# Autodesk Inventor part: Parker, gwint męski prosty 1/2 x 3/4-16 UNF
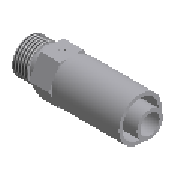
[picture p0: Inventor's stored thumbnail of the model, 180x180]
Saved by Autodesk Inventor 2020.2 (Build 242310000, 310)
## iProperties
IsCustomPart: 0
Company: Fabian Stasiak CAD Consulting
Manager: www.cadconsulting.pl
Created: 2014-02
Part Number: Parker, gwint męski prosty 1/2 x 3/4-16 UNF
Material: Stal
Description: Parker, łącznik
Document SubType Name: Modeling
Standard: Parker
Designer: F.Stasiak
Manufacturer: Parker
Language: pl-PL
Size Designation: 1/2 x 3/4-16 UNF
Categories: <MemberInstance><Categories><Category DisplayName="Rury cienko- i grubościenne" InternalName="4347fa0f-2144-441d-94cd-e3e15c92b736" Mnemonic="TUBEANDPIPE"><Cate
Density: 7.86 g/cm^3
Appearance: Płyta
Catalog Web Link: www.expertbooks.pl
NAME: PIPING: Parker Male Straight Thread
DATA: <meta><inlinegroups number="1" deflen="7.0358"></inlinegroups><connections number="2"></connections><angles><a>3.14159265358979</a></angles></meta>
Author: F.Stasiak
Subject: Zbiór ćwiczeń. Autodesk Inventor 2020. Kurs Professional
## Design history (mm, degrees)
sketch "Sketch1"
  geometry: L1 (0, 13.59)-(0, 3.51) reference; L2 (-14.176, 0)-(85.056, 0) reference; L3 (0, 4.95)-(0, 9.525); L4 (0, 9.525)-(8.6, 9.525); L5 (8.6, 9.525)-(8.6, 8.579); L6 (8.6, 8.579)-(10.725, 8.579); L7 (10.725, 8.579)-(10.725, 11.113); L8 (10.725, 11.113)-(23.984, 11.113); L9 (23.984, 11.113)-(23.984, 11.5); L10 (23.984, 11.5)-(27.784, 11.5); L11 (27.784, 11.5)-(27.784, 12.15); L12 (27.784, 12.15)-(62.484, 12.15); L13 (62.484, 12.15)-(62.484, 11.25); L14 (62.484, 11.25)-(35.18, 11.25); L15 (35.18, 11.25)-(35.18, 10.05); L16 (35.18, 10.05)-(30.48, 10.05); L17 (30.48, 10.05)-(30.48, 6.65); L18 (30.48, 6.65)-(70.88, 6.65); L19 (70.88, 6.65)-(70.88, 4.95); L20 (70.88, 4.95)-(0, 4.95)
  constraints: 36 end point, 14 parallel, 3 perpendicular, 1 point on line
  dimensions: "d0" = 9.9 diameter of L20 L2 (= HOLE); "d1" = 13.3 diameter of L18 L2 (= P1); "d2" = 20.1 diameter of L16 L2 (= U1); "d3" = 22.5 diameter of L14 L2 (= V1); "d4" = 24.3 diameter of L12 L2 (= SHELL_CRIMP); "d5" = 62.484 distance between parallel lines of L13 L1 (= A1); "d6" = 13.2588 distance between parallel lines of L7 L9 (= F1); "d7" = 23 diameter of L10 L2 (= O1); "d8" = 22.225 diameter of L8 L2 (= H1); "d9" = 40.4 distance between parallel lines of L17 L19 (= W1); "d10" = 4.7 distance between parallel lines of L15 L17 (= S1 - T1); "d11" = 38.5 distance between parallel lines of L9 L13 (= R1); "d12" = 3.8 distance between parallel lines of L11 L9 (= T1); "d13" = 30.48 distance between parallel lines of L17 L1 (= B1); "d14" = 19.05 diameter of L4 L2 (= Mt); "d15" = 17.1577 diameter of L6 L2 (= MD); "d16" = 8.6 distance between parallel lines of L5 L3 (= Lt)
revolve "Revolution1" sketch "Sketch1" stored, may be unused: angle "d21" = 90 deg
sketch "Sketch2"
  geometry: L1 (6.416, 11.113)-(12.832, 0); L2 (12.832, 0)-(6.416, -11.113); L3 (6.416, -11.113)-(-6.416, -11.113); L4 (-6.416, -11.113)-(-12.832, 0); L5 (-12.832, 0)-(-6.416, 11.113); L6 (-6.416, 11.113)-(6.416, 11.113); C1 r 8.579 at (0, 0) reference; 4 further points
  constraints: 12 end point, 2 coincident, 2 vertical alignment, 1 horizontal, 1 midpoint, 14 other
extrude "Extrusion1" join sketch "Sketch2" distance "d17" = 13.2588 (= F1); taper "d18" = 0 deg
sketch "Sketch3"
  geometry: L1 (0, 12.832)-(0, 0) reference; L2 (-24.901, 6.416)-(74.331, 6.416) reference; L3 (5.529, 7.516)-(6.929, 7.516); L4 (7.529, 6.916)-(7.529, 5.916); L5 (6.929, 5.316)-(5.829, 5.316); L6 (5.529, 5.016)-(5.529, 4.316); L7 (5.829, 4.316)-(5.829, 5.016); L8 (5.829, 5.016)-(6.929, 5.016); L9 (7.829, 5.916)-(7.829, 6.916); L10 (6.929, 7.816)-(5.529, 7.816); L11 (5.529, 7.816)-(5.529, 7.516); L12 (5.529, 4.316)-(5.829, 4.316); L13 (6.629, 6.716)-(4.329, 6.716); L14 (4.329, 6.716)-(4.329, 6.416); L15 (4.329, 6.416)-(6.629, 6.416); L16 (6.629, 6.416)-(6.629, 6.716); A1 r 0.6 centre (6.929, 6.916) between (7.529, 6.916) and (6.929, 7.516); A2 r 0.3 centre (5.829, 5.016) between (5.829, 5.316) and (5.529, 5.016); A3 r 0.6 centre (6.929, 5.916) between (6.929, 5.316) and (7.529, 5.916); A4 r 0.9 centre (6.929, 5.916) between (6.929, 5.016) and (7.829, 5.916); A5 r 0.9 centre (6.929, 6.916) between (7.829, 6.916) and (6.929, 7.816); 1 further point
  constraints: 28 end point, 10 point on circle, 7 parallel, 6 tangent, 5 centre point, 5 perpendicular, 1 equal radius, 1 horizontal, 1 midpoint, 1 point on line, 10 other
  dimensions: "d19" = 0.6 radius of A1 (= L_G); "d20" = 0.3 radius of A2 (= L_H); "d22" = 0.3 distance between parallel lines of L7 L6 (= L_H); "d23" = 2 distance between parallel lines of L11 L4 (= L_E); "d26" = 2 distance between parallel lines of L6 L4 (= L_E); "d27" = 2.2 distance between parallel lines of L5 L3 (= L_B); "d28" = 3.2 distance between parallel lines of L12 L3 (= L_A); "d29" = 0.3 distance between parallel lines of L15 L13 (= L_H); "d30" = 0.9 distance between parallel lines of L16 L4 (= L_F); "d31" = 3.2 distance between parallel lines of L14 L4 (= L_D); "d32" = 1.1 distance between parallel lines of L15 L3 (= L_C); "d33" = 6.6294 distance between parallel lines of L16 L1 (= 0.5 x F1)
emboss "Emboss1" sketch "Sketch3" dims "d0" = 9.9 (= HOLE), "d1" = 13.3 (= P1), "d2" = 20.1 (= U1), "d3" = 22.5 (= V1), "d4" = 24.3 (= SHELL_CRIMP), "d5" = 62.484 (= A1), "d6" = 13.2588 (= F1), "d7" = 23 (= O1), "d8" = 22.225 (= H1), "d9" = 40.4 (= W1), "d10" = 4.7 (= S1 - T1), "d11" = 38.5 (= R1), "d12" = 3.8 (= T1), "d13" = 30.48 (= B1), "d14" = 19.05 (= Mt), "d15" = 17.1577 (= MD), "d16" = 8.6 (= Lt), "d34" = 0.2, "d94" = 0
sketch "Sketch4"
  geometry: L1 (0, 12.832)-(0, 0) reference; L2 (13.259, 0)-(13.259, 3.456) reference; L3 (7.729, 5.316)-(6.329, 5.316); L4 (5.729, 5.916)-(5.729, 6.916); L5 (6.329, 7.516)-(7.429, 7.516); L6 (7.729, 7.816)-(7.729, 8.516); L7 (7.429, 8.516)-(7.429, 7.816); L8 (7.429, 7.816)-(6.329, 7.816); L9 (5.429, 6.916)-(5.429, 5.916); L10 (6.329, 5.016)-(7.729, 5.016); L11 (7.729, 5.316)-(7.729, 5.016); L12 (7.729, 8.516)-(7.429, 8.516); L13 (6.629, 6.116)-(8.929, 6.116); L14 (8.929, 6.116)-(8.929, 6.416); L15 (8.929, 6.416)-(6.629, 6.416); L16 (6.629, 6.416)-(6.629, 6.116); L17 (74.331, 6.416)-(-24.901, 6.416) reference; A1 r 0.6 centre (6.329, 5.916) between (5.729, 5.916) and (6.329, 5.316); A2 r 0.6 centre (6.329, 6.916) between (6.329, 7.516) and (5.729, 6.916); A3 r 0.3 centre (7.429, 7.816) between (7.429, 7.516) and (7.729, 7.816); A4 r 0.9 centre (6.329, 6.916) between (6.329, 7.816) and (5.429, 6.916); A5 r 0.9 centre (6.329, 5.916) between (5.429, 5.916) and (6.329, 5.016); 1 further point
  constraints: 28 end point, 10 point on circle, 6 parallel, 6 perpendicular, 6 tangent, 5 centre point, 1 equal radius, 1 horizontal, 1 midpoint, 1 point on line, 10 other
  dimensions: "d35" = 0.6 radius of A1 (= L_G); "d36" = 0.3 radius of A3 (= L_H); "d37" = 0.3 distance between parallel lines of L6 L7 (= L_H); "d38" = 2.2 distance between parallel lines of L5 L3 (= L_B); "d39" = 3.2 distance between parallel lines of L12 L3 (= L_A); "d40" = 2 distance between parallel lines of L11 L4 (= L_E); "d41" = 2 distance between parallel lines of L6 L4 (= L_E); "d42" = 0.3 distance between parallel lines of L15 L13 (= L_H); "d43" = 0.9 distance between parallel lines of L16 L4 (= L_F); "d44" = 3.2 distance between parallel lines of L14 L4 (= L_D); "d45" = 1.1 distance between parallel lines of L15 L3 (= L_C); "d46" = 6.6294 distance between parallel lines of L16 L1 (= 0.5 x F1)
emboss "Emboss2" sketch "Sketch4" dims "d0" = 9.9 (= HOLE), "d1" = 13.3 (= P1), "d2" = 20.1 (= U1), "d3" = 22.5 (= V1), "d4" = 24.3 (= SHELL_CRIMP), "d5" = 62.484 (= A1), "d6" = 13.2588 (= F1), "d7" = 23 (= O1), "d8" = 22.225 (= H1), "d9" = 40.4 (= W1), "d10" = 4.7 (= S1 - T1), "d11" = 38.5 (= R1), "d12" = 3.8 (= T1), "d13" = 30.48 (= B1), "d14" = 19.05 (= Mt), "d15" = 17.1577 (= MD), "d16" = 8.6 (= Lt), "d47" = 0.2, "d108" = 0
workaxis "Work Axis1"
workpoint "Work Point1"
workaxis "Work Axis2"
workpoint "Work Point2"
workaxis "Work Axis3"
workaxis "Work Axis4"
workpoint "Work Point3"
workpoint "Work Point4"
body "Solid1"
feature "Gwint1" dims "d24" = 25.4, "d25" = 0
other parameters: "A1" = 62.484 [user parameter; used in 1 equation term], "B1" = 30.48 [user parameter; used in 1 equation term], "H1" = 22.225 [user parameter; used in 1 equation term], "F1" = 13.2588 [user parameter; used in 4 equation terms], "Mt" = 19.05 [user parameter; used in 1 equation term], "Lt" = 8.6 [user parameter; used in 1 equation term], "MD" = 17.1577 [user parameter; used in 1 equation term], "O1" = 23 [user parameter; used in 1 equation term], "P1" = 13.3 [user parameter; used in 1 equation term], "R1" = 38.5 [user parameter; used in 1 equation term], "S1" = 8.5 [user parameter; used in 1 equation term], "T1" = 3.8 [user parameter; used in 2 equation terms], "U1" = 20.1 [user parameter; used in 1 equation term], "V1" = 22.5 [user parameter; used in 1 equation term], "W1" = 40.4 [user parameter; used in 1 equation term], "HOLE" = 9.9 [user parameter; used in 1 equation term], "SHELL_CRIMP" = 24.3 [user parameter; used in 1 equation term], "L_A" = 3.2 [user parameter; used in 2 equation terms], "L_B" = 2.2 [user parameter; used in 2 equation terms], "L_C" = 1.1 [user parameter; used in 2 equation terms], "L_D" = 3.2 [user parameter; used in 2 equation terms], "L_E" = 2 [user parameter; used in 4 equation terms], "L_F" = 0.9 [user parameter; used in 2 equation terms], "L_G" = 0.6 [user parameter; used in 2 equation terms], "L_H" = 0.3 [user parameter; used in 6 equation terms], "Size_Designation" = 12.345 [user parameter]
